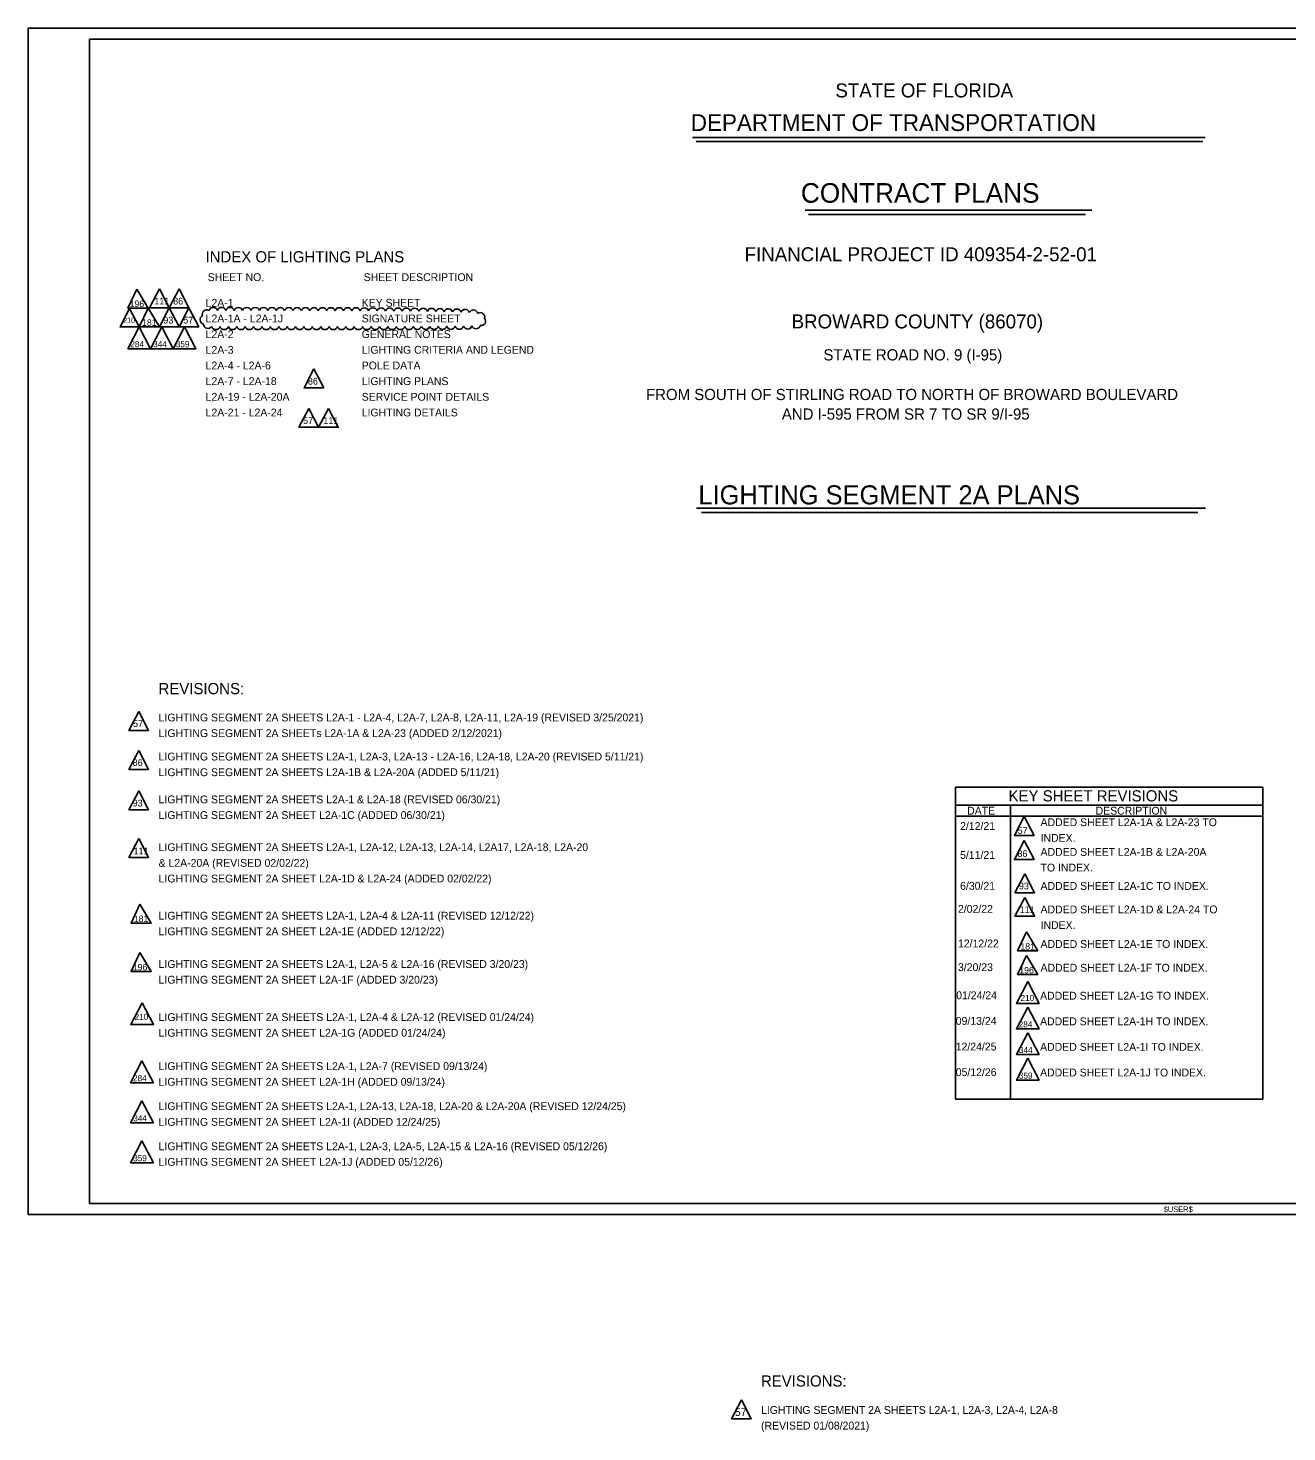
# Model space of a CAD drawing. Extents: x -820.2 to -798.7, y -2201.1 to -2188.5.
# Drawn here: x -820.23 to -808.98, y -2201.07 to -2188.52 of the extents above; entities that cross this region are included whole.
import ezdxf

# ---------------------------------------------------------------- set-up
doc = ezdxf.new("R2010")
doc.units = 0
for name, color, linetype in [('AdhocPoint_dp', 7, 'Continuous'), ('Cloud_dp', 7, 'Continuous'), ('PlotBorder_dp', 7, 'Continuous'), ('SheetBorder_dp', 7, 'Continuous'), ('SumBoxLines_dp', 7, 'Continuous'), ('TextLabel', 7, 'Continuous'), ('TextMinor', 7, 'Continuous'), ('TextNotes', 7, 'Continuous'), ('TextTitle', 7, 'Continuous')]:
    doc.layers.add(name, color=color, linetype=linetype)

msp = doc.modelspace()

# ---------------------------------------------------------------- linework, layer by layer
at = {"layer": 'AdhocPoint_dp'}
msp.add_line((-820.227, -2199.124), (-820.227, -2199.124), dxfattribs=at)
at = {"layer": 'Cloud_dp'}
for points in [[(-819.256, -2190.857), (-819.335, -2191.025), (-819.155, -2191.025)], [(-819.053, -2190.854), (-819.141, -2191.023), (-818.965, -2191.023)], [(-818.877, -2190.854), (-818.965, -2191.023), (-818.789, -2191.023)], [(-819.319, -2191.028), (-819.405, -2191.193), (-819.234, -2191.193)], [(-819.155, -2191.025), (-819.234, -2191.193), (-819.053, -2191.193)], [(-818.965, -2191.023), (-819.053, -2191.193), (-818.877, -2191.193)], [(-818.789, -2191.023), (-818.877, -2191.193), (-818.701, -2191.193)], [(-819.234, -2191.193), (-819.335, -2191.388), (-819.132, -2191.388)], [(-819.031, -2191.193), (-819.132, -2191.388), (-818.93, -2191.388)], [(-818.828, -2191.193), (-818.93, -2191.388), (-818.727, -2191.388)], [(-817.672, -2191.569), (-817.76, -2191.739), (-817.584, -2191.739)], [(-817.718, -2191.921), (-817.806, -2192.09), (-817.63, -2192.09)], [(-817.542, -2191.921), (-817.63, -2192.09), (-817.454, -2192.09)], [(-819.238, -2194.629), (-819.326, -2194.798), (-819.15, -2194.798)], [(-819.238, -2194.977), (-819.326, -2195.147), (-819.15, -2195.147)], [(-819.238, -2195.338), (-819.326, -2195.508), (-819.15, -2195.508)], [(-811.324, -2195.567), (-811.412, -2195.736), (-811.236, -2195.736)], [(-819.238, -2195.765), (-819.326, -2195.935), (-819.15, -2195.935)], [(-811.324, -2195.783), (-811.412, -2195.953), (-811.236, -2195.953)], [(-811.319, -2196.08), (-811.407, -2196.249), (-811.231, -2196.249)], [(-811.319, -2196.29), (-811.407, -2196.459), (-811.231, -2196.459)], [(-819.228, -2196.352), (-819.307, -2196.52), (-819.126, -2196.52)], [(-811.305, -2196.599), (-811.384, -2196.767), (-811.203, -2196.767)], [(-819.228, -2196.784), (-819.307, -2196.952), (-819.126, -2196.952)], [(-811.305, -2196.811), (-811.384, -2196.979), (-811.203, -2196.979)], [(-811.293, -2197.042), (-811.394, -2197.237), (-811.191, -2197.237)], [(-819.207, -2197.231), (-819.309, -2197.427), (-819.106, -2197.427)], [(-811.293, -2197.27), (-811.394, -2197.465), (-811.191, -2197.465)], [(-811.293, -2197.499), (-811.394, -2197.694), (-811.191, -2197.694)], [(-819.209, -2197.751), (-819.31, -2197.946), (-819.107, -2197.946)], [(-811.293, -2197.728), (-811.394, -2197.923), (-811.191, -2197.923)], [(-819.209, -2198.109), (-819.31, -2198.304), (-819.107, -2198.304)], [(-819.209, -2198.466), (-819.31, -2198.661), (-819.107, -2198.661)], [(-813.851, -2200.779), (-813.939, -2200.949), (-813.763, -2200.949)]]:
    msp.add_lwpolyline(points, close=True, dxfattribs=at)
for centre, radius, start, end in [((-818.631, -2191.079), 0.0393, 57.4429, 202.4429), ((-818.572, -2191.058), 0.0393, 17.4254, 162.4254), ((-818.497, -2191.058), 0.0393, 17.3487, 162.3487), ((-818.422, -2191.058), 0.0393, 17.3487, 162.3487), ((-818.347, -2191.059), 0.0393, 17.3487, 162.3487), ((-818.272, -2191.059), 0.0393, 17.3487, 162.3487), ((-818.197, -2191.059), 0.0393, 17.3487, 162.3487), ((-818.122, -2191.059), 0.0393, 17.3487, 162.3487), ((-818.047, -2191.059), 0.0393, 17.3487, 162.3487), ((-817.972, -2191.06), 0.0393, 17.3487, 162.3487), ((-817.897, -2191.06), 0.0393, 17.3487, 162.3487), ((-817.822, -2191.06), 0.0393, 17.3487, 162.3487), ((-817.747, -2191.06), 0.0393, 17.3487, 162.3487), ((-817.671, -2191.06), 0.0393, 17.3487, 162.3487), ((-817.596, -2191.061), 0.0393, 17.3487, 162.3487), ((-817.521, -2191.061), 0.0393, 17.3487, 162.3487), ((-817.446, -2191.061), 0.0393, 17.3487, 162.3487), ((-817.371, -2191.061), 0.0393, 17.3304, 162.3304), ((-817.296, -2191.061), 0.0393, 17.2888, 162.2888), ((-817.221, -2191.062), 0.0393, 17.2428, 162.2428), ((-817.146, -2191.062), 0.0393, 17.1914, 162.1914), ((-817.071, -2191.063), 0.0393, 17.1336, 162.1336), ((-816.996, -2191.063), 0.0393, 17.0679, 162.0679), ((-816.921, -2191.064), 0.0393, 16.9923, 161.9923), ((-816.846, -2191.064), 0.0393, 16.904, 161.904), ((-816.771, -2191.065), 0.0393, 16.799, 161.799), ((-816.696, -2191.066), 0.0393, 16.6713, 161.6713), ((-816.621, -2191.067), 0.0393, 16.5114, 161.5114), ((-816.546, -2191.069), 0.0393, 16.3028, 161.3028), ((-816.471, -2191.071), 0.0393, 16.0143, 161.0143), ((-816.396, -2191.073), 0.0393, 15.5766, 160.5766), ((-816.321, -2191.076), 0.0393, 14.7862, 159.7862), ((-816.247, -2191.081), 0.0394, 12.403, 157.403), ((-816.185, -2191.104), 0.0393, 341.3099, 126.3099), ((-818.651, -2191.13), 0.0393, 113.8298, 258.8298), ((-818.619, -2191.168), 0.0393, 180.98, 325.98), ((-818.549, -2191.178), 0.0393, 197.5, 342.5), ((-818.474, -2191.178), 0.0393, 197.5, 342.5), ((-818.399, -2191.178), 0.0393, 197.5, 342.5), ((-818.324, -2191.178), 0.0393, 197.5, 342.5), ((-818.249, -2191.178), 0.0393, 197.5, 342.5), ((-818.174, -2191.178), 0.0393, 197.5, 342.5), ((-818.099, -2191.178), 0.0393, 197.5, 342.5), ((-818.024, -2191.178), 0.0393, 197.5, 342.5), ((-817.949, -2191.178), 0.0393, 197.5, 342.5), ((-817.874, -2191.178), 0.0393, 197.5, 342.5), ((-817.799, -2191.178), 0.0393, 197.5, 342.5), ((-817.724, -2191.178), 0.0393, 197.5, 342.5), ((-817.649, -2191.178), 0.0393, 197.5, 342.5), ((-817.574, -2191.178), 0.0393, 197.5, 342.5), ((-817.499, -2191.178), 0.0393, 197.5, 342.5), ((-817.424, -2191.178), 0.0393, 197.5, 342.5), ((-817.349, -2191.178), 0.0393, 197.5052, 342.5052), ((-817.274, -2191.178), 0.0393, 197.5223, 342.5223), ((-817.199, -2191.178), 0.0393, 197.5417, 342.5417), ((-817.123, -2191.178), 0.0393, 197.5633, 342.5633), ((-817.048, -2191.178), 0.0393, 197.5876, 342.5876), ((-816.973, -2191.178), 0.0393, 197.6153, 342.6153), ((-816.898, -2191.178), 0.0393, 197.6471, 342.6471), ((-816.823, -2191.178), 0.0393, 197.6843, 342.6843), ((-816.748, -2191.177), 0.0393, 197.7285, 342.7285), ((-816.673, -2191.177), 0.0393, 197.7822, 342.7822), ((-816.598, -2191.177), 0.0393, 197.8496, 342.8496), ((-816.523, -2191.176), 0.0393, 197.9376, 342.9376), ((-816.448, -2191.176), 0.0393, 198.0595, 343.0595), ((-816.373, -2191.175), 0.0393, 198.2448, 343.2448), ((-816.298, -2191.173), 0.0393, 198.5811, 343.5811), ((-816.223, -2191.171), 0.0394, 199.6227, 344.6227), ((-816.177, -2191.143), 0.0393, 257.5478, 42.5478)]:
    msp.add_arc(centre, radius, start, end, dxfattribs=at)
at = {"layer": 'PlotBorder_dp'}
msp.add_lwpolyline([(-820.227, -2199.124), (-803.727, -2199.124), (-803.727, -2188.524), (-820.227, -2188.524)], close=True, dxfattribs=at)
at = {"layer": 'SheetBorder_dp'}
for p, q in [((-819.677, -2188.624), (-819.677, -2199.024)), ((-819.677, -2188.624), (-804.277, -2188.624)), ((-819.677, -2199.024), (-804.277, -2199.024))]:
    msp.add_line(p, q, dxfattribs=at)
at = {"layer": 'SumBoxLines_dp'}
for p, q in [((-811.938, -2195.306), (-811.938, -2198.092)), ((-811.938, -2195.306), (-809.191, -2195.306)), ((-809.191, -2195.306), (-809.191, -2198.092)), ((-811.938, -2195.466), (-809.191, -2195.466)), ((-811.938, -2195.566), (-809.191, -2195.566)), ((-811.448, -2195.466), (-811.448, -2198.092)), ((-811.938, -2198.092), (-809.191, -2198.092))]:
    msp.add_line(p, q, dxfattribs=at)
at = {"layer": 'TextTitle'}
for p, q in [((-814.289, -2189.5), (-809.707, -2189.5)), ((-814.257, -2189.538), (-809.729, -2189.538)), ((-813.281, -2190.15), (-810.719, -2190.15)), ((-813.253, -2190.188), (-810.777, -2190.188)), ((-814.252, -2192.813), (-809.704, -2192.813)), ((-814.209, -2192.851), (-809.772, -2192.851))]:
    msp.add_line(p, q, dxfattribs=at)

# ---------------------------------------------------------------- texts
at = {"layer": 'Cloud_dp'}
for s, height, p in [('111', 0.06, (-819.099, -2190.993)), ('86', 0.06, (-818.93, -2190.993)), ('93', 0.06, (-819.018, -2191.163)), ('57', 0.06, (-818.84, -2191.163)), ('86', 0.06, (-817.726, -2191.709)), ('57', 0.06, (-817.769, -2192.06)), ('111', 0.06, (-817.588, -2192.06)), ('57', 0.06, (-819.289, -2194.768)), ('86', 0.06, (-819.292, -2195.116)), ('93', 0.06, (-819.292, -2195.478)), ('57', 0.06, (-811.383, -2195.722)), ('111', 0.06, (-819.284, -2195.905)), ('86', 0.06, (-811.385, -2195.929)), ('93', 0.06, (-811.372, -2196.219)), ('111', 0.06, (-811.364, -2196.429)), ('57', 0.07, (-813.91, -2200.924))]:
    msp.add_text(s, height=height, rotation=0, dxfattribs=at).set_placement(p)
for s, height, p in [('196', 0.0582, (-819.32, -2191.016)), ('210', 0.0461, (-819.377, -2191.157)), ('181', 0.0582, (-819.208, -2191.184)), ('284', 0.0547, (-819.313, -2191.375)), ('344', 0.0547, (-819.109, -2191.375)), ('359', 0.0547, (-818.907, -2191.375)), ('181', 0.0582, (-819.282, -2196.511)), ('181', 0.0582, (-811.358, -2196.758)), ('196', 0.0582, (-819.291, -2196.943)), ('196', 0.0582, (-811.368, -2196.97)), ('210', 0.0547, (-811.357, -2197.217)), ('210', 0.0547, (-819.275, -2197.385)), ('284', 0.0547, (-811.373, -2197.452)), ('344', 0.0547, (-811.371, -2197.681)), ('284', 0.0547, (-819.289, -2197.933)), ('359', 0.0547, (-811.372, -2197.91)), ('344', 0.0547, (-819.287, -2198.291)), ('359', 0.0547, (-819.288, -2198.648))]:
    msp.add_text(s, height=height, dxfattribs=at).set_placement(p)
at = {"layer": 'TextLabel'}
for s, height, p in [('INDEX OF LIGHTING PLANS', 0.1, (-818.641, -2190.617)), ('FINANCIAL PROJECT ID 409354-2-52-01', 0.125, (-813.823, -2190.607)), ('L2A-1', 0.07, (-818.64, -2191.013)), ('KEY SHEET', 0.07, (-817.245, -2191.013)), ('L2A-1A - L2A-1J', 0.07, (-818.64, -2191.153)), ('SIGNATURE SHEET', 0.07, (-817.245, -2191.153)), ('BROWARD COUNTY (86070)', 0.125, (-813.403, -2191.207)), ('L2A-2', 0.07, (-818.64, -2191.293)), ('GENERAL NOTES', 0.07, (-817.245, -2191.293)), ('L2A-3', 0.07, (-818.64, -2191.433)), ('LIGHTING CRITERIA AND LEGEND', 0.07, (-817.245, -2191.433)), ('STATE ROAD NO. 9 (I-95)', 0.1, (-813.118, -2191.493)), ('L2A-4 - L2A-6 ', 0.07, (-818.64, -2191.573)), ('POLE DATA', 0.07, (-817.245, -2191.573)), ('L2A-7 - L2A-18', 0.07, (-818.64, -2191.713)), ('LIGHTING PLANS', 0.07, (-817.245, -2191.713)), ('L2A-19 - L2A-20A', 0.07, (-818.64, -2191.853)), ('SERVICE POINT DETAILS', 0.07, (-817.245, -2191.853)), ('FROM SOUTH OF STIRLING ROAD TO NORTH OF BROWARD BOULEVARD', 0.1, (-814.704, -2191.847)), ('L2A-21 - L2A-24', 0.07, (-818.64, -2191.993)), ('LIGHTING DETAILS', 0.07, (-817.245, -2191.993)), ('AND I-595 FROM SR 7 TO SR 9/I-95', 0.1, (-813.49, -2192.022)), ('REVISIONS:', 0.1, (-819.061, -2194.475)), ('KEY SHEET REVISIONS', 0.1, (-811.464, -2195.433)), ('REVISIONS:', 0.1, (-813.677, -2200.661))]:
    msp.add_text(s, height=height, dxfattribs=at).set_placement(p)
at = {"layer": 'TextMinor'}
for s, height, p in [('ADDED SHEET L2A-1A & L2A-23 TO ', 0.07, (-811.178, -2195.654)), ('2/12/21', 0.07, (-811.897, -2195.688)), ('INDEX.', 0.07, (-811.178, -2195.794)), ('5/11/21', 0.07, (-811.897, -2195.946)), ('ADDED SHEET L2A-1B & L2A-20A ', 0.07, (-811.178, -2195.919)), ('TO INDEX.', 0.07, (-811.178, -2196.059)), ('6/30/21', 0.07, (-811.897, -2196.222)), ('ADDED SHEET L2A-1C TO INDEX.', 0.07, (-811.178, -2196.223)), ('2/02/22', 0.07, (-811.916, -2196.428)), ('ADDED SHEET L2A-1D & L2A-24 TO ', 0.07, (-811.178, -2196.433)), ('INDEX.', 0.07, (-811.178, -2196.573)), ('12/12/22', 0.07, (-811.916, -2196.737)), ('ADDED SHEET L2A-1E TO INDEX.', 0.07, (-811.178, -2196.742)), ('3/20/23', 0.07, (-811.916, -2196.949)), ('ADDED SHEET L2A-1F TO INDEX.', 0.07, (-811.178, -2196.954)), ('01/24/24', 0.07, (-811.932, -2197.2)), ('ADDED SHEET L2A-1G TO INDEX.', 0.07, (-811.182, -2197.204)), ('09/13/24', 0.07, (-811.936, -2197.429)), ('ADDED SHEET L2A-1H TO INDEX.', 0.07, (-811.182, -2197.433)), ('12/24/25', 0.07, (-811.936, -2197.658)), ('ADDED SHEET L2A-1I TO INDEX.', 0.07, (-811.182, -2197.661)), ('05/12/26', 0.07, (-811.936, -2197.887)), ('ADDED SHEET L2A-1J TO INDEX.', 0.07, (-811.182, -2197.89)), ('$USER$', 0.05, (-810.078, -2199.102))]:
    msp.add_text(s, height=height, dxfattribs=at).set_placement(p)
at = {"layer": 'TextNotes'}
for s, height, p in [('SHEET NO.', 0.07, (-818.621, -2190.784)), ('SHEET DESCRIPTION', 0.07, (-817.227, -2190.784)), ('LIGHTING SEGMENT 2A SHEETS L2A-1 - L2A-4, L2A-7, L2A-8, L2A-11, L2A-19 (REVISED 3/25/2021)', 0.06998, (-819.06, -2194.718)), ('LIGHTING SEGMENT 2A SHEETs L2A-1A & L2A-23 (ADDED 2/12/2021)', 0.06998, (-819.06, -2194.858)), ('LIGHTING SEGMENT 2A SHEETS L2A-1, L2A-3, L2A-13 - L2A-16, L2A-18, L2A-20 (REVISED 5/11/21)', 0.06998, (-819.06, -2195.067)), ('LIGHTING SEGMENT 2A SHEETS L2A-1B & L2A-20A (ADDED 5/11/21)', 0.06998, (-819.06, -2195.207)), ('LIGHTING SEGMENT 2A SHEETS L2A-1 & L2A-18 (REVISED 06/30/21)', 0.06998, (-819.06, -2195.45)), ('LIGHTING SEGMENT 2A SHEET L2A-1C (ADDED 06/30/21)', 0.06998, (-819.06, -2195.59)), ('DATE', 0.07, (-811.834, -2195.551)), ('DESCRIPTION', 0.07, (-810.686, -2195.551)), ('LIGHTING SEGMENT 2A SHEETS L2A-1, L2A-12, L2A-13, L2A-14, L2A17, L2A-18, L2A-20 ', 0.06998, (-819.06, -2195.877)), ('& L2A-20A (REVISED 02/02/22)', 0.06998, (-819.06, -2196.017)), ('LIGHTING SEGMENT 2A SHEET L2A-1D & L2A-24 (ADDED 02/02/22)', 0.06998, (-819.06, -2196.157)), ('LIGHTING SEGMENT 2A SHEETS L2A-1, L2A-4 & L2A-11 (REVISED 12/12/22)', 0.06998, (-819.06, -2196.489)), ('LIGHTING SEGMENT 2A SHEET L2A-1E (ADDED 12/12/22)', 0.06998, (-819.06, -2196.629)), ('LIGHTING SEGMENT 2A SHEETS L2A-1, L2A-5 & L2A-16 (REVISED 3/20/23)', 0.06998, (-819.06, -2196.921)), ('LIGHTING SEGMENT 2A SHEET L2A-1F (ADDED 3/20/23)', 0.06998, (-819.06, -2197.061)), ('LIGHTING SEGMENT 2A SHEETS L2A-1, L2A-4 & L2A-12 (REVISED 01/24/24)', 0.06998, (-819.06, -2197.395)), ('LIGHTING SEGMENT 2A SHEET L2A-1G (ADDED 01/24/24)', 0.06998, (-819.06, -2197.535)), ('LIGHTING SEGMENT 2A SHEETS L2A-1, L2A-7 (REVISED 09/13/24)', 0.06998, (-819.06, -2197.833)), ('LIGHTING SEGMENT 2A SHEET L2A-1H (ADDED 09/13/24)', 0.06998, (-819.06, -2197.973)), ('LIGHTING SEGMENT 2A SHEETS L2A-1, L2A-13, L2A-18, L2A-20 & L2A-20A (REVISED 12/24/25)', 0.06998, (-819.06, -2198.191)), ('LIGHTING SEGMENT 2A SHEET L2A-1I (ADDED 12/24/25)', 0.06998, (-819.06, -2198.331)), ('LIGHTING SEGMENT 2A SHEETS L2A-1, L2A-3, L2A-5, L2A-15 & L2A-16 (REVISED 05/12/26)', 0.06998, (-819.06, -2198.549)), ('LIGHTING SEGMENT 2A SHEET L2A-1J (ADDED 05/12/26)', 0.06998, (-819.06, -2198.688)), ('LIGHTING SEGMENT 2A SHEETS L2A-1, L2A-3, L2A-4, L2A-8 ', 0.07, (-813.676, -2200.905)), ('(REVISED 01/08/2021)', 0.07, (-813.676, -2201.045))]:
    msp.add_text(s, height=height, dxfattribs=at).set_placement(p)
at = {"layer": 'TextTitle'}
for s, height, p in [('STATE OF FLORIDA', 0.125, (-813.012, -2189.143)), ('DEPARTMENT OF TRANSPORTATION', 0.15, (-814.304, -2189.443)), ('CONTRACT PLANS', 0.175, (-813.32, -2190.084)), ('LIGHTING SEGMENT 2A PLANS', 0.17, (-814.236, -2192.779))]:
    msp.add_text(s, height=height, dxfattribs=at).set_placement(p)

doc.saveas('drawing.dxf')
